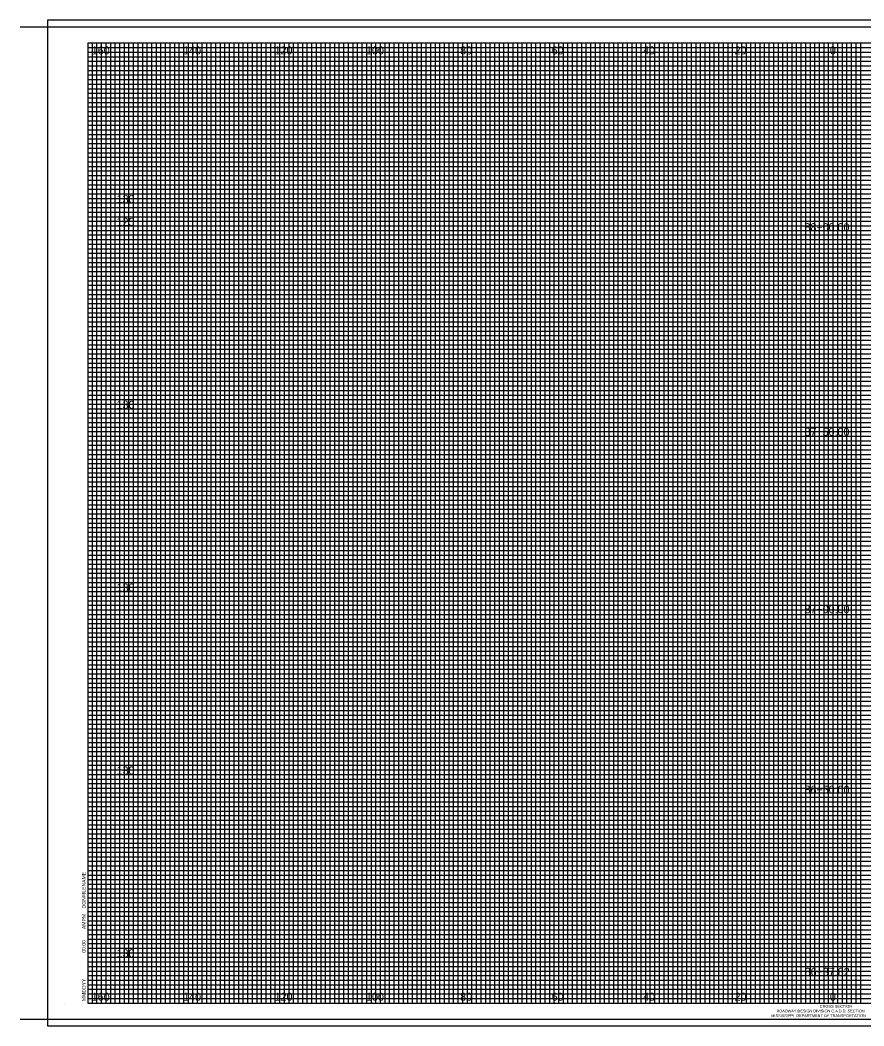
# Model space of a CAD drawing. Extents: x -3604 to 2303, y -13 to 9543.
# Drawn here: x -3604.5 to -3420, y 5304.1 to 5524.1 of the extents above; entities that cross this region are included whole.
import ezdxf

# ---------------------------------------------------------------- set-up
doc = ezdxf.new("R2010")
doc.units = 0
for name, color, linetype in [('SHEET_BORDER', 7, 'Continuous'), ('SHEET_BORDER_TX', 7, 'Continuous'), ('SHEET_DATE_DGN_TX', 7, 'Continuous'), ('SHEET_PLOTTING_SHAPE', 7, 'Continuous'), ('XS_SHEET_LABELS_ELEVATION', 7, 'Continuous'), ('XS_SHEET_LABELS_OFFSET', 7, 'Continuous'), ('XS_SHEET_LABELS_STATION', 7, 'Continuous'), ('XS_SHEET_MAJOR_GRIDS', 7, 'Continuous'), ('XS_SHEET_MEDIUM_GRIDS', 7, 'Continuous'), ('XS_SHEET_MINOR_GRIDS', 7, 'Continuous')]:
    doc.layers.add(name, color=color, linetype=linetype)

msp = doc.modelspace()

# ---------------------------------------------------------------- linework, layer by layer
at = {"layer": 'SHEET_BORDER'}
for p, q in [((-3604.48, 5522.59), (-3252.48, 5522.59)), ((-3589.68, 5519.09), (-3254.68, 5519.09)), ((-3589.68, 5519.09), (-3589.68, 5309.09)), ((-3445.68, 5309.09), (-3445.68, 5519.09)), ((-3594.68, 5309.09), (-3594.68, 5309.09)), ((-3589.68, 5309.09), (-3254.68, 5309.09)), ((-3604.48, 5305.59), (-3252.48, 5305.59))]:
    msp.add_line(p, q, dxfattribs=at)
at = {"layer": 'SHEET_PLOTTING_SHAPE'}
msp.add_lwpolyline([(-3598.48, 5304.09), (-3252.48, 5304.09), (-3252.48, 5524.09), (-3598.48, 5524.09)], close=True, dxfattribs=at)
at = {"layer": 'XS_SHEET_MAJOR_GRIDS'}
for p, q in [((-3584.68, 5309.09), (-3584.68, 5519.09)), ((-3574.68, 5309.09), (-3574.68, 5519.09)), ((-3564.68, 5309.09), (-3564.68, 5519.09)), ((-3554.68, 5309.09), (-3554.68, 5519.09)), ((-3544.68, 5309.09), (-3544.68, 5519.09)), ((-3534.68, 5309.09), (-3534.68, 5519.09)), ((-3524.68, 5309.09), (-3524.68, 5519.09)), ((-3514.68, 5309.09), (-3514.68, 5519.09)), ((-3504.68, 5309.09), (-3504.68, 5519.09)), ((-3494.68, 5309.09), (-3494.68, 5519.09)), ((-3484.68, 5309.09), (-3484.68, 5519.09)), ((-3474.68, 5309.09), (-3474.68, 5519.09)), ((-3464.68, 5309.09), (-3464.68, 5519.09)), ((-3454.68, 5309.09), (-3454.68, 5519.09)), ((-3444.68, 5309.09), (-3444.68, 5519.09)), ((-3434.68, 5309.09), (-3434.68, 5519.09)), ((-3424.68, 5309.09), (-3424.68, 5519.09)), ((-3589.68, 5509.09), (-3254.68, 5509.09)), ((-3589.68, 5499.09), (-3254.68, 5499.09)), ((-3589.68, 5489.09), (-3254.68, 5489.09)), ((-3589.68, 5479.09), (-3254.68, 5479.09)), ((-3589.68, 5469.09), (-3254.68, 5469.09)), ((-3589.68, 5459.09), (-3254.68, 5459.09)), ((-3589.68, 5449.09), (-3254.68, 5449.09)), ((-3589.68, 5439.09), (-3254.68, 5439.09)), ((-3589.68, 5429.09), (-3254.68, 5429.09)), ((-3589.68, 5419.09), (-3254.68, 5419.09)), ((-3589.68, 5409.09), (-3254.68, 5409.09)), ((-3589.68, 5399.09), (-3254.68, 5399.09)), ((-3589.68, 5389.09), (-3254.68, 5389.09)), ((-3589.68, 5379.09), (-3254.68, 5379.09)), ((-3589.68, 5369.09), (-3254.68, 5369.09)), ((-3589.68, 5359.09), (-3254.68, 5359.09)), ((-3589.68, 5349.09), (-3254.68, 5349.09)), ((-3589.68, 5339.09), (-3254.68, 5339.09)), ((-3589.68, 5329.09), (-3254.68, 5329.09)), ((-3589.68, 5319.09), (-3254.68, 5319.09))]:
    msp.add_line(p, q, dxfattribs=at)
at = {"layer": 'XS_SHEET_MEDIUM_GRIDS'}
for p, q in [((-3579.68, 5309.09), (-3579.68, 5519.09)), ((-3569.68, 5309.09), (-3569.68, 5519.09)), ((-3559.68, 5309.09), (-3559.68, 5519.09)), ((-3549.68, 5309.09), (-3549.68, 5519.09)), ((-3539.68, 5309.09), (-3539.68, 5519.09)), ((-3529.68, 5309.09), (-3529.68, 5519.09)), ((-3519.68, 5309.09), (-3519.68, 5519.09)), ((-3509.68, 5309.09), (-3509.68, 5519.09)), ((-3499.68, 5309.09), (-3499.68, 5519.09)), ((-3489.68, 5309.09), (-3489.68, 5519.09)), ((-3479.68, 5309.09), (-3479.68, 5519.09)), ((-3469.68, 5309.09), (-3469.68, 5519.09)), ((-3459.68, 5309.09), (-3459.68, 5519.09)), ((-3449.68, 5309.09), (-3449.68, 5519.09)), ((-3439.68, 5309.09), (-3439.68, 5519.09)), ((-3429.68, 5309.09), (-3429.68, 5519.09)), ((-3589.68, 5514.09), (-3281.68, 5514.09)), ((-3589.68, 5504.09), (-3254.68, 5504.09)), ((-3589.68, 5494.09), (-3254.68, 5494.09)), ((-3589.68, 5484.09), (-3254.68, 5484.09)), ((-3589.68, 5474.09), (-3254.68, 5474.09)), ((-3589.68, 5464.09), (-3254.68, 5464.09)), ((-3589.68, 5454.09), (-3254.68, 5454.09)), ((-3589.68, 5444.09), (-3254.68, 5444.09)), ((-3589.68, 5434.09), (-3254.68, 5434.09)), ((-3589.68, 5424.09), (-3254.68, 5424.09)), ((-3589.68, 5414.09), (-3254.68, 5414.09)), ((-3589.68, 5404.09), (-3254.68, 5404.09)), ((-3589.68, 5394.09), (-3254.68, 5394.09)), ((-3589.68, 5384.09), (-3254.68, 5384.09)), ((-3589.68, 5374.09), (-3254.68, 5374.09)), ((-3589.68, 5364.09), (-3254.68, 5364.09)), ((-3589.68, 5354.09), (-3254.68, 5354.09)), ((-3589.68, 5344.09), (-3254.68, 5344.09)), ((-3589.68, 5334.09), (-3254.68, 5334.09)), ((-3589.68, 5324.09), (-3254.68, 5324.09)), ((-3589.68, 5314.09), (-3264.68, 5314.09))]:
    msp.add_line(p, q, dxfattribs=at)
at = {"layer": 'XS_SHEET_MINOR_GRIDS'}
for p, q in [((-3589.68, 5518.09), (-3281.68, 5518.09)), ((-3588.68, 5309.09), (-3588.68, 5519.09)), ((-3587.68, 5309.09), (-3587.68, 5519.09)), ((-3586.68, 5309.09), (-3586.68, 5519.09)), ((-3585.68, 5309.09), (-3585.68, 5519.09)), ((-3583.68, 5309.09), (-3583.68, 5519.09)), ((-3582.68, 5309.09), (-3582.68, 5519.09)), ((-3581.68, 5309.09), (-3581.68, 5519.09)), ((-3580.68, 5309.09), (-3580.68, 5519.09)), ((-3578.68, 5309.09), (-3578.68, 5519.09)), ((-3577.68, 5309.09), (-3577.68, 5519.09)), ((-3576.68, 5309.09), (-3576.68, 5519.09)), ((-3575.68, 5309.09), (-3575.68, 5519.09)), ((-3573.68, 5309.09), (-3573.68, 5519.09)), ((-3572.68, 5309.09), (-3572.68, 5519.09)), ((-3571.68, 5309.09), (-3571.68, 5519.09)), ((-3570.68, 5309.09), (-3570.68, 5519.09)), ((-3568.68, 5309.09), (-3568.68, 5519.09)), ((-3567.68, 5309.09), (-3567.68, 5519.09)), ((-3566.68, 5309.09), (-3566.68, 5519.09)), ((-3565.68, 5309.09), (-3565.68, 5519.09)), ((-3563.68, 5309.09), (-3563.68, 5519.09)), ((-3562.68, 5309.09), (-3562.68, 5519.09)), ((-3561.68, 5309.09), (-3561.68, 5519.09)), ((-3560.68, 5309.09), (-3560.68, 5519.09)), ((-3558.68, 5309.09), (-3558.68, 5519.09)), ((-3557.68, 5309.09), (-3557.68, 5519.09)), ((-3556.68, 5309.09), (-3556.68, 5519.09)), ((-3555.68, 5309.09), (-3555.68, 5519.09)), ((-3553.68, 5309.09), (-3553.68, 5519.09)), ((-3552.68, 5309.09), (-3552.68, 5519.09)), ((-3551.68, 5309.09), (-3551.68, 5519.09)), ((-3550.68, 5309.09), (-3550.68, 5519.09)), ((-3548.68, 5309.09), (-3548.68, 5519.09)), ((-3547.68, 5309.09), (-3547.68, 5519.09)), ((-3546.68, 5309.09), (-3546.68, 5519.09)), ((-3545.68, 5309.09), (-3545.68, 5519.09)), ((-3543.68, 5309.09), (-3543.68, 5519.09)), ((-3542.68, 5309.09), (-3542.68, 5519.09)), ((-3541.68, 5309.09), (-3541.68, 5519.09)), ((-3540.68, 5309.09), (-3540.68, 5519.09)), ((-3538.68, 5309.09), (-3538.68, 5519.09)), ((-3537.68, 5309.09), (-3537.68, 5519.09)), ((-3536.68, 5309.09), (-3536.68, 5519.09)), ((-3535.68, 5309.09), (-3535.68, 5519.09)), ((-3533.68, 5309.09), (-3533.68, 5519.09)), ((-3532.68, 5309.09), (-3532.68, 5519.09)), ((-3531.68, 5309.09), (-3531.68, 5519.09)), ((-3530.68, 5309.09), (-3530.68, 5519.09)), ((-3528.68, 5309.09), (-3528.68, 5519.09)), ((-3527.68, 5309.09), (-3527.68, 5519.09)), ((-3526.68, 5309.09), (-3526.68, 5519.09)), ((-3525.68, 5309.09), (-3525.68, 5519.09)), ((-3523.68, 5309.09), (-3523.68, 5519.09)), ((-3522.68, 5309.09), (-3522.68, 5519.09)), ((-3521.68, 5309.09), (-3521.68, 5519.09)), ((-3520.68, 5309.09), (-3520.68, 5519.09)), ((-3518.68, 5309.09), (-3518.68, 5519.09)), ((-3517.68, 5309.09), (-3517.68, 5519.09)), ((-3516.68, 5309.09), (-3516.68, 5519.09)), ((-3515.68, 5309.09), (-3515.68, 5519.09)), ((-3513.68, 5309.09), (-3513.68, 5519.09)), ((-3512.68, 5309.09), (-3512.68, 5519.09)), ((-3511.68, 5309.09), (-3511.68, 5519.09)), ((-3510.68, 5309.09), (-3510.68, 5519.09)), ((-3508.68, 5309.09), (-3508.68, 5519.09)), ((-3507.68, 5309.09), (-3507.68, 5519.09)), ((-3506.68, 5309.09), (-3506.68, 5519.09)), ((-3505.68, 5309.09), (-3505.68, 5519.09)), ((-3503.68, 5309.09), (-3503.68, 5519.09)), ((-3502.68, 5309.09), (-3502.68, 5519.09)), ((-3501.68, 5309.09), (-3501.68, 5519.09)), ((-3500.68, 5309.09), (-3500.68, 5519.09)), ((-3498.68, 5309.09), (-3498.68, 5519.09)), ((-3497.68, 5309.09), (-3497.68, 5519.09)), ((-3496.68, 5309.09), (-3496.68, 5519.09)), ((-3495.68, 5309.09), (-3495.68, 5519.09)), ((-3493.68, 5309.09), (-3493.68, 5519.09)), ((-3492.68, 5309.09), (-3492.68, 5519.09)), ((-3491.68, 5309.09), (-3491.68, 5519.09)), ((-3490.68, 5309.09), (-3490.68, 5519.09)), ((-3488.68, 5309.09), (-3488.68, 5519.09)), ((-3487.68, 5309.09), (-3487.68, 5519.09)), ((-3486.68, 5309.09), (-3486.68, 5519.09)), ((-3485.68, 5309.09), (-3485.68, 5519.09)), ((-3483.68, 5309.09), (-3483.68, 5519.09)), ((-3482.68, 5309.09), (-3482.68, 5519.09)), ((-3481.68, 5309.09), (-3481.68, 5519.09)), ((-3480.68, 5309.09), (-3480.68, 5519.09)), ((-3478.68, 5309.09), (-3478.68, 5519.09)), ((-3477.68, 5309.09), (-3477.68, 5519.09)), ((-3476.68, 5309.09), (-3476.68, 5519.09)), ((-3475.68, 5309.09), (-3475.68, 5519.09)), ((-3473.68, 5309.09), (-3473.68, 5519.09)), ((-3472.68, 5309.09), (-3472.68, 5519.09)), ((-3471.68, 5309.09), (-3471.68, 5519.09)), ((-3470.68, 5309.09), (-3470.68, 5519.09)), ((-3468.68, 5309.09), (-3468.68, 5519.09)), ((-3467.68, 5309.09), (-3467.68, 5519.09)), ((-3466.68, 5309.09), (-3466.68, 5519.09)), ((-3465.68, 5309.09), (-3465.68, 5519.09)), ((-3463.68, 5309.09), (-3463.68, 5519.09)), ((-3462.68, 5309.09), (-3462.68, 5519.09)), ((-3461.68, 5309.09), (-3461.68, 5519.09)), ((-3460.68, 5309.09), (-3460.68, 5519.09)), ((-3458.68, 5309.09), (-3458.68, 5519.09)), ((-3457.68, 5309.09), (-3457.68, 5519.09)), ((-3456.68, 5309.09), (-3456.68, 5519.09)), ((-3455.68, 5309.09), (-3455.68, 5519.09)), ((-3453.68, 5309.09), (-3453.68, 5519.09)), ((-3452.68, 5309.09), (-3452.68, 5519.09)), ((-3451.68, 5309.09), (-3451.68, 5519.09)), ((-3450.68, 5309.09), (-3450.68, 5519.09)), ((-3448.68, 5309.09), (-3448.68, 5519.09)), ((-3447.68, 5309.09), (-3447.68, 5519.09)), ((-3446.68, 5309.09), (-3446.68, 5519.09)), ((-3443.68, 5309.09), (-3443.68, 5519.09)), ((-3442.68, 5309.09), (-3442.68, 5519.09)), ((-3441.68, 5309.09), (-3441.68, 5519.09)), ((-3440.68, 5309.09), (-3440.68, 5519.09)), ((-3438.68, 5309.09), (-3438.68, 5519.09)), ((-3437.68, 5309.09), (-3437.68, 5519.09)), ((-3436.68, 5309.09), (-3436.68, 5519.09)), ((-3435.68, 5309.09), (-3435.68, 5519.09)), ((-3433.68, 5309.09), (-3433.68, 5519.09)), ((-3432.68, 5309.09), (-3432.68, 5519.09)), ((-3431.68, 5309.09), (-3431.68, 5519.09)), ((-3430.68, 5309.09), (-3430.68, 5519.09)), ((-3428.68, 5309.09), (-3428.68, 5519.09)), ((-3427.68, 5309.09), (-3427.68, 5519.09)), ((-3426.68, 5309.09), (-3426.68, 5519.09)), ((-3425.68, 5309.09), (-3425.68, 5519.09)), ((-3423.68, 5309.09), (-3423.68, 5519.09)), ((-3422.68, 5309.09), (-3422.68, 5519.09)), ((-3421.68, 5309.09), (-3421.68, 5519.09)), ((-3420.68, 5309.09), (-3420.68, 5519.09)), ((-3589.68, 5517.09), (-3281.68, 5517.09)), ((-3589.68, 5516.09), (-3281.68, 5516.09)), ((-3589.68, 5515.09), (-3281.68, 5515.09)), ((-3589.68, 5513.09), (-3281.68, 5513.09)), ((-3589.68, 5512.09), (-3281.68, 5512.09)), ((-3589.68, 5511.09), (-3281.68, 5511.09)), ((-3589.68, 5510.09), (-3254.68, 5510.09)), ((-3589.68, 5508.09), (-3254.68, 5508.09)), ((-3589.68, 5507.09), (-3254.68, 5507.09)), ((-3589.68, 5506.09), (-3254.68, 5506.09)), ((-3589.68, 5505.09), (-3254.68, 5505.09)), ((-3589.68, 5503.09), (-3254.68, 5503.09)), ((-3589.68, 5502.09), (-3254.68, 5502.09)), ((-3589.68, 5501.09), (-3254.68, 5501.09)), ((-3589.68, 5500.09), (-3254.68, 5500.09)), ((-3589.68, 5498.09), (-3254.68, 5498.09)), ((-3589.68, 5497.09), (-3254.68, 5497.09)), ((-3589.68, 5496.09), (-3254.68, 5496.09)), ((-3589.68, 5495.09), (-3254.68, 5495.09)), ((-3589.68, 5493.09), (-3254.68, 5493.09)), ((-3589.68, 5492.09), (-3254.68, 5492.09)), ((-3589.68, 5491.09), (-3254.68, 5491.09)), ((-3589.68, 5490.09), (-3254.68, 5490.09)), ((-3589.68, 5488.09), (-3254.68, 5488.09)), ((-3589.68, 5487.09), (-3254.68, 5487.09)), ((-3589.68, 5486.09), (-3254.68, 5486.09)), ((-3589.68, 5485.09), (-3254.68, 5485.09)), ((-3589.68, 5483.09), (-3254.68, 5483.09)), ((-3589.68, 5482.09), (-3254.68, 5482.09)), ((-3589.68, 5481.09), (-3254.68, 5481.09)), ((-3589.68, 5480.09), (-3254.68, 5480.09)), ((-3589.68, 5478.09), (-3254.68, 5478.09)), ((-3589.68, 5477.09), (-3254.68, 5477.09)), ((-3589.68, 5476.09), (-3254.68, 5476.09)), ((-3589.68, 5475.09), (-3254.68, 5475.09)), ((-3589.68, 5473.09), (-3254.68, 5473.09)), ((-3589.68, 5472.09), (-3254.68, 5472.09)), ((-3589.68, 5471.09), (-3254.68, 5471.09)), ((-3589.68, 5470.09), (-3254.68, 5470.09)), ((-3589.68, 5468.09), (-3254.68, 5468.09)), ((-3589.68, 5467.09), (-3254.68, 5467.09)), ((-3589.68, 5466.09), (-3254.68, 5466.09)), ((-3589.68, 5465.09), (-3254.68, 5465.09)), ((-3589.68, 5463.09), (-3254.68, 5463.09)), ((-3589.68, 5462.09), (-3254.68, 5462.09)), ((-3589.68, 5461.09), (-3254.68, 5461.09)), ((-3589.68, 5460.09), (-3254.68, 5460.09)), ((-3589.68, 5458.09), (-3254.68, 5458.09)), ((-3589.68, 5457.09), (-3254.68, 5457.09)), ((-3589.68, 5456.09), (-3254.68, 5456.09)), ((-3589.68, 5455.09), (-3254.68, 5455.09)), ((-3589.68, 5453.09), (-3254.68, 5453.09)), ((-3589.68, 5452.09), (-3254.68, 5452.09)), ((-3589.68, 5451.09), (-3254.68, 5451.09)), ((-3589.68, 5450.09), (-3254.68, 5450.09)), ((-3589.68, 5448.09), (-3254.68, 5448.09)), ((-3589.68, 5447.09), (-3254.68, 5447.09)), ((-3589.68, 5446.09), (-3254.68, 5446.09)), ((-3589.68, 5445.09), (-3254.68, 5445.09)), ((-3589.68, 5443.09), (-3254.68, 5443.09)), ((-3589.68, 5442.09), (-3254.68, 5442.09)), ((-3589.68, 5441.09), (-3254.68, 5441.09)), ((-3589.68, 5440.09), (-3254.68, 5440.09)), ((-3589.68, 5438.09), (-3254.68, 5438.09)), ((-3589.68, 5437.09), (-3254.68, 5437.09)), ((-3589.68, 5436.09), (-3254.68, 5436.09)), ((-3589.68, 5435.09), (-3254.68, 5435.09)), ((-3589.68, 5433.09), (-3254.68, 5433.09)), ((-3589.68, 5432.09), (-3254.68, 5432.09)), ((-3589.68, 5431.09), (-3254.68, 5431.09)), ((-3589.68, 5430.09), (-3254.68, 5430.09)), ((-3589.68, 5428.09), (-3254.68, 5428.09)), ((-3589.68, 5427.09), (-3254.68, 5427.09)), ((-3589.68, 5426.09), (-3254.68, 5426.09)), ((-3589.68, 5425.09), (-3254.68, 5425.09)), ((-3589.68, 5423.09), (-3254.68, 5423.09)), ((-3589.68, 5422.09), (-3254.68, 5422.09)), ((-3589.68, 5421.09), (-3254.68, 5421.09)), ((-3589.68, 5420.09), (-3254.68, 5420.09)), ((-3589.68, 5418.09), (-3254.68, 5418.09)), ((-3589.68, 5417.09), (-3254.68, 5417.09)), ((-3589.68, 5416.09), (-3254.68, 5416.09)), ((-3589.68, 5415.09), (-3254.68, 5415.09)), ((-3589.68, 5413.09), (-3254.68, 5413.09)), ((-3589.68, 5412.09), (-3254.68, 5412.09)), ((-3589.68, 5411.09), (-3254.68, 5411.09)), ((-3589.68, 5410.09), (-3254.68, 5410.09)), ((-3589.68, 5408.09), (-3254.68, 5408.09)), ((-3589.68, 5407.09), (-3254.68, 5407.09)), ((-3589.68, 5406.09), (-3254.68, 5406.09)), ((-3589.68, 5405.09), (-3254.68, 5405.09)), ((-3589.68, 5403.09), (-3254.68, 5403.09)), ((-3589.68, 5402.09), (-3254.68, 5402.09)), ((-3589.68, 5401.09), (-3254.68, 5401.09)), ((-3589.68, 5400.09), (-3254.68, 5400.09)), ((-3589.68, 5398.09), (-3254.68, 5398.09)), ((-3589.68, 5397.09), (-3254.68, 5397.09)), ((-3589.68, 5396.09), (-3254.68, 5396.09)), ((-3589.68, 5395.09), (-3254.68, 5395.09)), ((-3589.68, 5393.09), (-3254.68, 5393.09)), ((-3589.68, 5392.09), (-3254.68, 5392.09)), ((-3589.68, 5391.09), (-3254.68, 5391.09)), ((-3589.68, 5390.09), (-3254.68, 5390.09)), ((-3589.68, 5388.09), (-3254.68, 5388.09)), ((-3589.68, 5387.09), (-3254.68, 5387.09)), ((-3589.68, 5386.09), (-3254.68, 5386.09)), ((-3589.68, 5385.09), (-3254.68, 5385.09)), ((-3589.68, 5383.09), (-3254.68, 5383.09)), ((-3589.68, 5382.09), (-3254.68, 5382.09)), ((-3589.68, 5381.09), (-3254.68, 5381.09)), ((-3589.68, 5380.09), (-3254.68, 5380.09)), ((-3589.68, 5378.09), (-3254.68, 5378.09)), ((-3589.68, 5377.09), (-3254.68, 5377.09)), ((-3589.68, 5376.09), (-3254.68, 5376.09)), ((-3589.68, 5375.09), (-3254.68, 5375.09)), ((-3589.68, 5373.09), (-3254.68, 5373.09)), ((-3589.68, 5372.09), (-3254.68, 5372.09)), ((-3589.68, 5371.09), (-3254.68, 5371.09)), ((-3589.68, 5370.09), (-3254.68, 5370.09)), ((-3589.68, 5368.09), (-3254.68, 5368.09)), ((-3589.68, 5367.09), (-3254.68, 5367.09)), ((-3589.68, 5366.09), (-3254.68, 5366.09)), ((-3589.68, 5365.09), (-3254.68, 5365.09)), ((-3589.68, 5363.09), (-3254.68, 5363.09)), ((-3589.68, 5362.09), (-3254.68, 5362.09)), ((-3589.68, 5361.09), (-3254.68, 5361.09)), ((-3589.68, 5360.09), (-3254.68, 5360.09)), ((-3589.68, 5358.09), (-3254.68, 5358.09)), ((-3589.68, 5357.09), (-3254.68, 5357.09)), ((-3589.68, 5356.09), (-3254.68, 5356.09)), ((-3589.68, 5355.09), (-3254.68, 5355.09)), ((-3589.68, 5353.09), (-3254.68, 5353.09)), ((-3589.68, 5352.09), (-3254.68, 5352.09)), ((-3589.68, 5351.09), (-3254.68, 5351.09)), ((-3589.68, 5350.09), (-3254.68, 5350.09)), ((-3589.68, 5348.09), (-3254.68, 5348.09)), ((-3589.68, 5347.09), (-3254.68, 5347.09)), ((-3589.68, 5346.09), (-3254.68, 5346.09)), ((-3589.68, 5345.09), (-3254.68, 5345.09)), ((-3589.68, 5343.09), (-3254.68, 5343.09)), ((-3589.68, 5342.09), (-3254.68, 5342.09)), ((-3589.68, 5341.09), (-3254.68, 5341.09)), ((-3589.68, 5340.09), (-3254.68, 5340.09)), ((-3589.68, 5338.09), (-3254.68, 5338.09)), ((-3589.68, 5337.09), (-3254.68, 5337.09)), ((-3589.68, 5336.09), (-3254.68, 5336.09)), ((-3589.68, 5335.09), (-3254.68, 5335.09)), ((-3589.68, 5333.09), (-3254.68, 5333.09)), ((-3589.68, 5332.09), (-3254.68, 5332.09)), ((-3589.68, 5331.09), (-3254.68, 5331.09)), ((-3589.68, 5330.09), (-3254.68, 5330.09)), ((-3589.68, 5330.09), (-3254.68, 5330.09)), ((-3589.68, 5330.09), (-3254.68, 5330.09)), ((-3589.68, 5328.09), (-3254.68, 5328.09)), ((-3589.68, 5327.09), (-3254.68, 5327.09)), ((-3589.68, 5326.09), (-3254.68, 5326.09)), ((-3589.68, 5325.09), (-3254.68, 5325.09)), ((-3589.68, 5323.09), (-3254.68, 5323.09)), ((-3589.68, 5322.09), (-3254.68, 5322.09)), ((-3589.68, 5321.09), (-3254.68, 5321.09)), ((-3589.68, 5320.09), (-3254.68, 5320.09)), ((-3589.68, 5318.09), (-3264.68, 5318.09)), ((-3589.68, 5317.09), (-3264.68, 5317.09)), ((-3589.68, 5316.09), (-3264.68, 5316.09)), ((-3589.68, 5315.09), (-3264.68, 5315.09)), ((-3589.68, 5315.09), (-3264.68, 5315.09)), ((-3589.68, 5315.09), (-3264.68, 5315.09)), ((-3589.68, 5313.09), (-3264.68, 5313.09)), ((-3589.68, 5312.09), (-3264.68, 5312.09)), ((-3589.68, 5311.09), (-3264.68, 5311.09)), ((-3589.68, 5310.09), (-3264.68, 5310.09))]:
    msp.add_line(p, q, dxfattribs=at)

# ---------------------------------------------------------------- texts
at = {"layer": 'SHEET_BORDER_TX'}
for s, height, p in [('CROSS SECTION', 0.62, (-3429.64, 5308.06)), ('MISSISSIPPI  DEPARTMENT OF TRANSPORTATION', 0.61, (-3440.24, 5306.01)), ('ROADWAY DESIGN DIVISION C.A.D.D. SECTION', 0.61, (-3439.08, 5307.04))]:
    msp.add_text(s, height=height, dxfattribs=at).set_placement(p)
at = {"layer": 'SHEET_DATE_DGN_TX'}
for s, p in [('DGNFILENAME', (-3590.15, 5329.79)), ('AMPM', (-3590.15, 5325.27)), ('00:00', (-3590.15, 5320.09)), ('MMDDYY', (-3590.15, 5309.51))]:
    msp.add_text(s, height=0.8, rotation=90, dxfattribs=at).set_placement(p)
at = {"layer": 'XS_SHEET_LABELS_ELEVATION'}
for s, p in [('  130  ', (-3584.68, 5484.09)), ('  125  ', (-3584.68, 5479.09)), ('  130  ', (-3584.68, 5439.09)), ('  130  ', (-3584.68, 5399.09)), ('  130  ', (-3584.68, 5359.09)), ('  130  ', (-3584.68, 5319.09))]:
    msp.add_text(s, height=1.75, dxfattribs=at).set_placement(p)
at = {"layer": 'XS_SHEET_LABELS_OFFSET'}
for s, p in [('  160  ', (-3590.11, 5516.59)), ('  140  ', (-3570.13, 5516.59)), ('  120  ', (-3550.13, 5516.59)), ('  100  ', (-3530.13, 5516.59)), ('  80  ', (-3509.56, 5516.59)), ('  60  ', (-3489.55, 5516.59)), ('  40  ', (-3469.56, 5516.59)), ('  20  ', (-3449.56, 5516.59)), ('  0  ', (-3428.71, 5516.59)), ('  0  ', (-3428.71, 5516.59)), ('  160  ', (-3590.11, 5309.59)), ('  140  ', (-3570.13, 5309.59)), ('  120  ', (-3550.13, 5309.59)), ('  100  ', (-3530.13, 5309.59)), ('  80  ', (-3509.56, 5309.59)), ('  60  ', (-3489.55, 5309.59)), ('  40  ', (-3469.56, 5309.59)), ('  20  ', (-3449.56, 5309.59)), ('  0  ', (-3428.71, 5309.59)), ('  0  ', (-3428.71, 5309.59))]:
    msp.add_text(s, height=1.75, dxfattribs=at).set_placement(p)
at = {"layer": 'XS_SHEET_LABELS_STATION'}
for s, p in [('  88+00.00  ', (-3434.26, 5477.92)), ('  87+50.00  ', (-3434.26, 5433.16)), ('  87+00.00  ', (-3434.26, 5394.36)), ('  86+50.00  ', (-3434.25, 5354.88)), ('  86+37.82  ', (-3434.22, 5315.04))]:
    msp.add_text(s, height=1.75, dxfattribs=at).set_placement(p)

doc.saveas('drawing.dxf')
